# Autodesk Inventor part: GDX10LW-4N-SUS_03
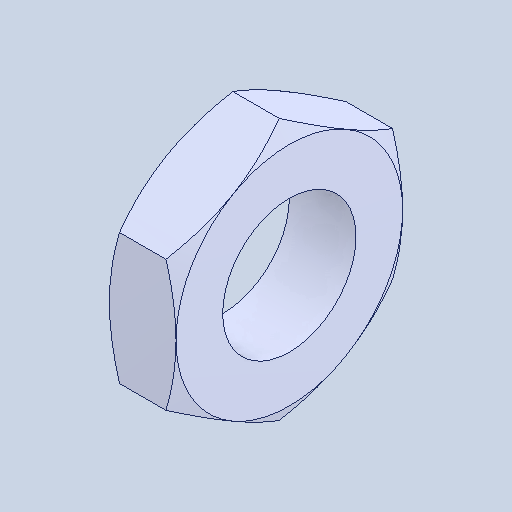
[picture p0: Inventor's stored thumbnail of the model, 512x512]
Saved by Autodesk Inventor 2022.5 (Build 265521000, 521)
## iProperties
Created: 2024-06
Part Number: GDX10LW-4N-SUS_03
Material: 一般
Document SubType Name: Modeling
Designer: ImaoCorp
Density: 1 g/cm^3
Appearance: 既定
Author: ImaoCorp
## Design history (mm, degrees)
feature "GDX10LW-4N-SUS_03"
node "ソリッド1"
